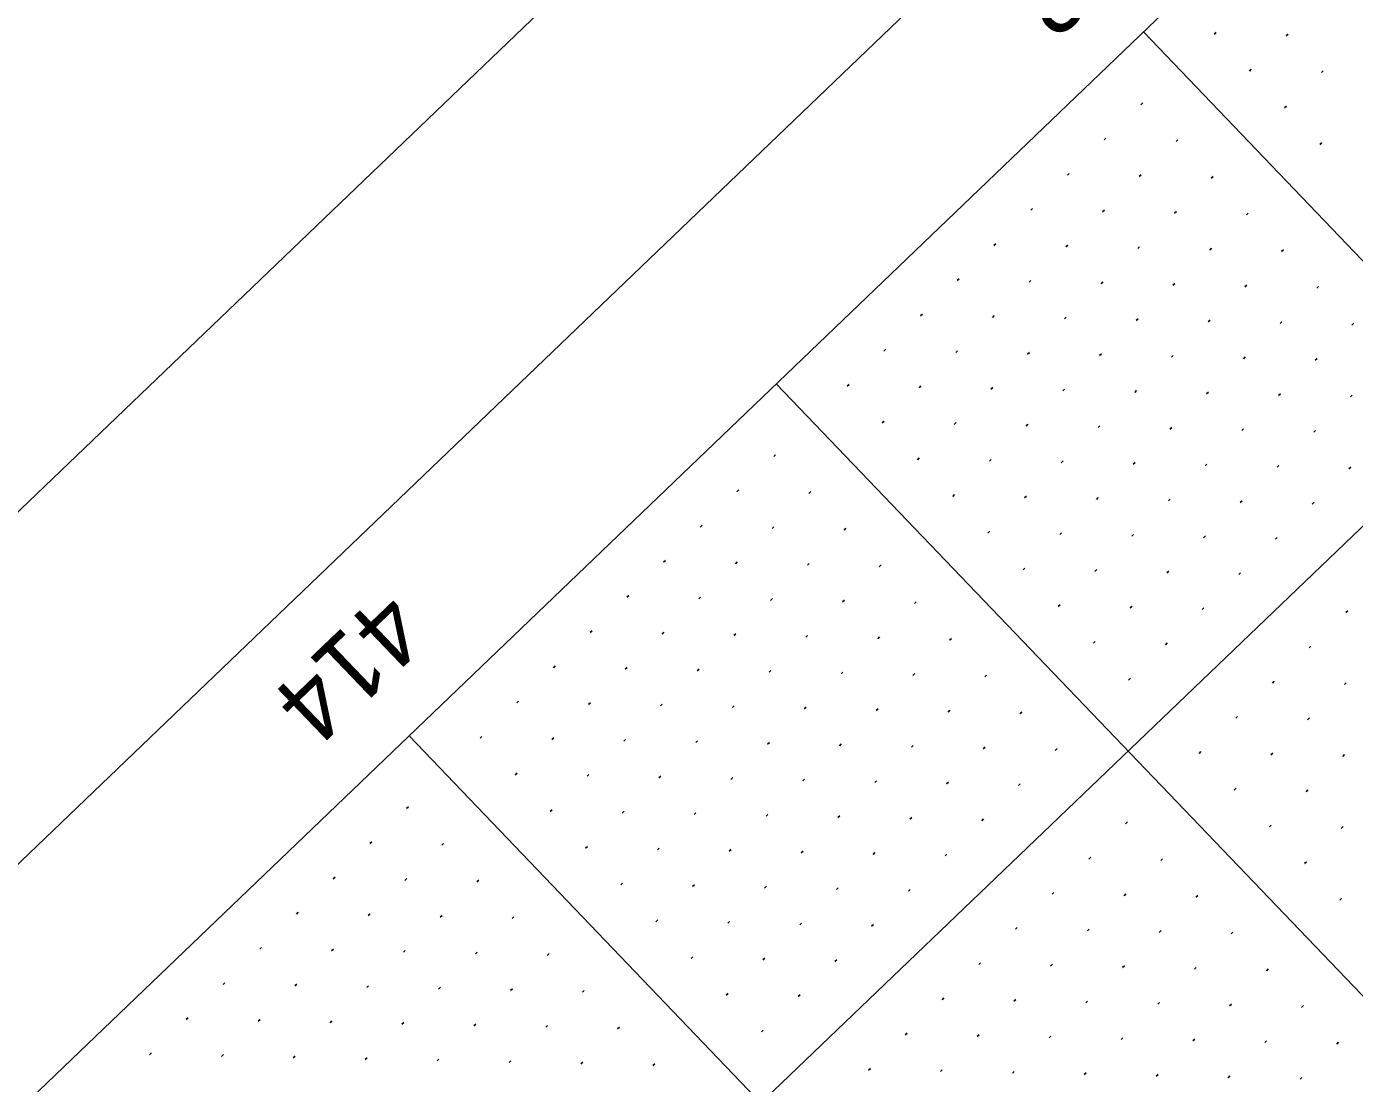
# Model space of a CAD drawing. Extents: x 2148987 to 2151117, y 142806 to 144993.
# Drawn here: x 2149512.9 to 2149643.5, y 144037.5 to 144141.4 of the extents above; entities that cross this region are included whole.
import ezdxf

# ---------------------------------------------------------------- set-up
doc = ezdxf.new("R2010")
doc.units = 0
for name, color, linetype in [('BASELINE', 7, 'Continuous'), ('PR_PIER_PH3', 7, 'Continuous'), ('PR_Road_Concrete', 7, 'Continuous'), ('SHT_Profile_Grid_Minor', 7, 'Continuous'), ('Wall D Bore Txt', 7, 'Continuous')]:
    doc.layers.add(name, color=color, linetype=linetype)

msp = doc.modelspace()

# ---------------------------------------------------------------- linework, layer by layer
at = {"layer": 'BASELINE'}
msp.add_lwpolyline([(2151029.45, 144024.32), (2149802.07, 142848.08), (2149040.98, 143642.27), (2150268.36, 144818.51)], close=True, dxfattribs=at)
at = {"layer": 'PR_PIER_PH3'}
for p, q in [((2150261.97, 144684.26), (2149124.83, 143594.52)), ((2149622.71, 144140.89), (2149916.82, 143833.99)), ((2149622.71, 144140.89), (2149916.82, 143833.99)), ((2149586.61, 144106.3), (2149932.56, 143745.3)), ((2149550.51, 144071.7), (2149896.46, 143710.71))]:
    msp.add_line(p, q, dxfattribs=at)
at = {"layer": 'PR_Road_Concrete'}
msp.add_line((2150227.37, 144720.36), (2149279.76, 143812.24), dxfattribs=at)
msp.add_lwpolyline([(2150941.76, 143974.91), (2149804.63, 142885.16), (2149078.13, 143643.25), (2150215.26, 144733)], close=True, dxfattribs=at)
at = {"layer": 'SHT_Profile_Grid_Minor'}
for p, q in [((2149629.86, 144140.83), (2149629.68, 144140.66)), ((2149636.93, 144140.68), (2149636.75, 144140.51)), ((2149633.32, 144137.22), (2149633.14, 144137.05)), ((2149640.39, 144137.07), (2149640.21, 144136.9)), ((2149622.64, 144133.91), (2149622.46, 144133.74)), ((2149636.78, 144133.61), (2149636.6, 144133.44)), ((2149619.03, 144130.45), (2149618.85, 144130.28)), ((2149626.1, 144130.3), (2149625.92, 144130.13)), ((2149640.24, 144130), (2149640.06, 144129.83)), ((2149615.42, 144126.99), (2149615.24, 144126.82)), ((2149622.49, 144126.84), (2149622.31, 144126.67)), ((2149629.56, 144126.69), (2149629.38, 144126.52)), ((2149611.81, 144123.53), (2149611.63, 144123.36)), ((2149618.88, 144123.38), (2149618.7, 144123.21)), ((2149625.95, 144123.23), (2149625.77, 144123.06)), ((2149633.02, 144123.08), (2149632.84, 144122.91)), ((2149608.2, 144120.07), (2149608.02, 144119.9)), ((2149615.27, 144119.92), (2149615.09, 144119.75)), ((2149622.34, 144119.77), (2149622.16, 144119.6)), ((2149629.41, 144119.62), (2149629.23, 144119.45)), ((2149636.48, 144119.47), (2149636.3, 144119.3)), ((2149604.6, 144116.61), (2149604.41, 144116.44)), ((2149611.66, 144116.46), (2149611.48, 144116.29)), ((2149618.73, 144116.31), (2149618.55, 144116.14)), ((2149625.8, 144116.16), (2149625.62, 144115.99)), ((2149632.87, 144116.01), (2149632.69, 144115.84)), ((2149639.94, 144115.86), (2149639.76, 144115.69)), ((2149600.99, 144113.15), (2149600.8, 144112.98)), ((2149608.05, 144113), (2149607.87, 144112.83)), ((2149615.12, 144112.85), (2149614.94, 144112.68)), ((2149622.19, 144112.7), (2149622.01, 144112.53)), ((2149629.26, 144112.55), (2149629.08, 144112.38)), ((2149636.33, 144112.4), (2149636.15, 144112.23)), ((2149643.4, 144112.25), (2149643.22, 144112.08)), ((2149597.38, 144109.7), (2149597.19, 144109.52)), ((2149604.44, 144109.54), (2149604.26, 144109.37)), ((2149611.51, 144109.39), (2149611.33, 144109.22)), ((2149618.58, 144109.24), (2149618.4, 144109.07)), ((2149625.65, 144109.09), (2149625.47, 144108.92)), ((2149632.72, 144108.94), (2149632.54, 144108.77)), ((2149639.79, 144108.79), (2149639.61, 144108.62)), ((2149593.77, 144106.24), (2149593.58, 144106.06)), ((2149600.83, 144106.09), (2149600.65, 144105.91)), ((2149607.9, 144105.93), (2149607.72, 144105.76)), ((2149614.97, 144105.78), (2149614.79, 144105.61)), ((2149622.04, 144105.63), (2149621.86, 144105.46)), ((2149629.11, 144105.48), (2149628.93, 144105.31)), ((2149636.18, 144105.33), (2149636, 144105.16)), ((2149643.25, 144105.18), (2149643.07, 144105.01)), ((2149597.22, 144102.63), (2149597.04, 144102.45)), ((2149604.29, 144102.48), (2149604.11, 144102.3)), ((2149611.36, 144102.33), (2149611.18, 144102.15)), ((2149618.43, 144102.17), (2149618.25, 144102)), ((2149625.5, 144102.02), (2149625.32, 144101.85)), ((2149632.57, 144101.87), (2149632.39, 144101.7)), ((2149639.64, 144101.72), (2149639.46, 144101.55)), ((2149586.55, 144099.32), (2149586.36, 144099.14)), ((2149600.68, 144099.02), (2149600.5, 144098.84)), ((2149607.75, 144098.87), (2149607.57, 144098.69)), ((2149614.82, 144098.72), (2149614.64, 144098.54)), ((2149621.89, 144098.56), (2149621.71, 144098.39)), ((2149628.96, 144098.41), (2149628.78, 144098.24)), ((2149636.03, 144098.26), (2149635.85, 144098.09)), ((2149643.1, 144098.11), (2149642.92, 144097.94)), ((2149582.94, 144095.86), (2149582.75, 144095.68)), ((2149590, 144095.71), (2149589.82, 144095.53)), ((2149604.14, 144095.41), (2149603.96, 144095.23)), ((2149611.21, 144095.26), (2149611.03, 144095.08)), ((2149618.28, 144095.11), (2149618.1, 144094.93)), ((2149625.35, 144094.95), (2149625.17, 144094.78)), ((2149632.42, 144094.8), (2149632.24, 144094.63)), ((2149639.49, 144094.65), (2149639.31, 144094.48)), ((2149579.33, 144092.4), (2149579.14, 144092.22)), ((2149586.39, 144092.25), (2149586.21, 144092.07)), ((2149593.46, 144092.1), (2149593.28, 144091.92)), ((2149607.6, 144091.8), (2149607.42, 144091.62)), ((2149614.67, 144091.65), (2149614.49, 144091.47)), ((2149621.74, 144091.5), (2149621.56, 144091.32)), ((2149628.81, 144091.34), (2149628.63, 144091.17)), ((2149635.88, 144091.19), (2149635.7, 144091.02)), ((2149575.72, 144088.94), (2149575.53, 144088.77)), ((2149582.78, 144088.79), (2149582.6, 144088.61)), ((2149589.85, 144088.64), (2149589.67, 144088.46)), ((2149596.92, 144088.49), (2149596.74, 144088.31)), ((2149611.06, 144088.19), (2149610.88, 144088.01)), ((2149618.13, 144088.04), (2149617.95, 144087.86)), ((2149625.2, 144087.89), (2149625.02, 144087.71)), ((2149632.27, 144087.73), (2149632.09, 144087.56)), ((2149572.11, 144085.48), (2149571.92, 144085.31)), ((2149579.17, 144085.33), (2149578.99, 144085.16)), ((2149586.24, 144085.18), (2149586.06, 144085)), ((2149593.31, 144085.03), (2149593.13, 144084.85)), ((2149600.38, 144084.88), (2149600.2, 144084.7)), ((2149614.52, 144084.58), (2149614.34, 144084.4)), ((2149621.59, 144084.43), (2149621.41, 144084.25)), ((2149628.66, 144084.28), (2149628.48, 144084.1)), ((2149642.8, 144083.97), (2149642.62, 144083.8)), ((2149568.5, 144082.02), (2149568.32, 144081.85)), ((2149575.56, 144081.87), (2149575.38, 144081.7)), ((2149582.63, 144081.72), (2149582.45, 144081.55)), ((2149589.7, 144081.57), (2149589.52, 144081.39)), ((2149596.77, 144081.42), (2149596.59, 144081.24)), ((2149603.84, 144081.27), (2149603.66, 144081.09)), ((2149617.98, 144080.97), (2149617.8, 144080.79)), ((2149625.05, 144080.82), (2149624.87, 144080.64)), ((2149639.19, 144080.51), (2149639.01, 144080.34)), ((2149564.89, 144078.56), (2149564.71, 144078.39)), ((2149571.96, 144078.41), (2149571.77, 144078.24)), ((2149579.02, 144078.26), (2149578.84, 144078.09)), ((2149586.09, 144078.11), (2149585.91, 144077.94)), ((2149593.16, 144077.96), (2149592.98, 144077.78)), ((2149600.23, 144077.81), (2149600.05, 144077.63)), ((2149607.3, 144077.66), (2149607.12, 144077.48)), ((2149621.44, 144077.36), (2149621.26, 144077.18)), ((2149635.58, 144077.06), (2149635.4, 144076.88)), ((2149642.65, 144076.9), (2149642.47, 144076.73)), ((2149561.28, 144075.1), (2149561.1, 144074.93)), ((2149568.35, 144074.95), (2149568.16, 144074.78)), ((2149575.41, 144074.8), (2149575.23, 144074.63)), ((2149582.48, 144074.65), (2149582.3, 144074.48)), ((2149589.55, 144074.5), (2149589.37, 144074.33)), ((2149596.62, 144074.35), (2149596.44, 144074.18)), ((2149603.69, 144074.2), (2149603.51, 144074.02)), ((2149610.76, 144074.05), (2149610.58, 144073.87)), ((2149631.97, 144073.6), (2149631.79, 144073.42)), ((2149639.04, 144073.45), (2149638.86, 144073.27)), ((2149557.67, 144071.64), (2149557.49, 144071.47)), ((2149564.74, 144071.49), (2149564.55, 144071.32)), ((2149571.8, 144071.34), (2149571.62, 144071.17)), ((2149578.87, 144071.19), (2149578.69, 144071.02)), ((2149585.94, 144071.04), (2149585.76, 144070.87)), ((2149593.01, 144070.89), (2149592.83, 144070.72)), ((2149600.08, 144070.74), (2149599.9, 144070.57)), ((2149607.15, 144070.59), (2149606.97, 144070.41)), ((2149614.22, 144070.44), (2149614.04, 144070.26)), ((2149628.36, 144070.14), (2149628.18, 144069.96)), ((2149635.43, 144069.99), (2149635.25, 144069.81)), ((2149642.5, 144069.84), (2149642.32, 144069.66)), ((2149561.13, 144068.03), (2149560.94, 144067.86)), ((2149568.19, 144067.88), (2149568.01, 144067.71)), ((2149575.26, 144067.73), (2149575.08, 144067.56)), ((2149582.33, 144067.58), (2149582.15, 144067.41)), ((2149589.4, 144067.43), (2149589.22, 144067.26)), ((2149596.47, 144067.28), (2149596.29, 144067.11)), ((2149603.54, 144067.13), (2149603.36, 144066.96)), ((2149610.61, 144066.98), (2149610.43, 144066.8)), ((2149631.82, 144066.53), (2149631.64, 144066.35)), ((2149638.89, 144066.38), (2149638.71, 144066.2)), ((2149550.45, 144064.72), (2149550.27, 144064.55)), ((2149564.58, 144064.42), (2149564.4, 144064.25)), ((2149571.65, 144064.27), (2149571.47, 144064.1)), ((2149578.72, 144064.12), (2149578.54, 144063.95)), ((2149585.79, 144063.97), (2149585.61, 144063.8)), ((2149592.86, 144063.82), (2149592.68, 144063.65)), ((2149599.93, 144063.67), (2149599.75, 144063.5)), ((2149607, 144063.52), (2149606.82, 144063.35)), ((2149621.14, 144063.22), (2149620.96, 144063.04)), ((2149635.28, 144062.92), (2149635.1, 144062.74)), ((2149642.35, 144062.77), (2149642.17, 144062.59)), ((2149546.84, 144061.26), (2149546.66, 144061.09)), ((2149553.91, 144061.11), (2149553.72, 144060.94)), ((2149568.04, 144060.81), (2149567.86, 144060.64)), ((2149575.11, 144060.66), (2149574.93, 144060.49)), ((2149582.18, 144060.51), (2149582, 144060.34)), ((2149589.25, 144060.36), (2149589.07, 144060.19)), ((2149596.32, 144060.21), (2149596.14, 144060.04)), ((2149603.39, 144060.06), (2149603.21, 144059.89)), ((2149617.53, 144059.76), (2149617.35, 144059.58)), ((2149624.6, 144059.61), (2149624.42, 144059.43)), ((2149638.74, 144059.31), (2149638.56, 144059.13)), ((2149543.23, 144057.8), (2149543.05, 144057.63)), ((2149550.3, 144057.65), (2149550.11, 144057.48)), ((2149557.36, 144057.5), (2149557.18, 144057.33)), ((2149571.5, 144057.2), (2149571.32, 144057.03)), ((2149578.57, 144057.05), (2149578.39, 144056.88)), ((2149585.64, 144056.9), (2149585.46, 144056.73)), ((2149592.71, 144056.75), (2149592.53, 144056.58)), ((2149599.78, 144056.6), (2149599.6, 144056.43)), ((2149613.92, 144056.3), (2149613.74, 144056.13)), ((2149620.99, 144056.15), (2149620.81, 144055.97)), ((2149628.06, 144056), (2149627.88, 144055.82)), ((2149642.2, 144055.7), (2149642.02, 144055.52)), ((2149539.62, 144054.34), (2149539.44, 144054.17)), ((2149546.69, 144054.19), (2149546.5, 144054.02)), ((2149553.75, 144054.04), (2149553.57, 144053.87)), ((2149560.82, 144053.89), (2149560.64, 144053.72)), ((2149574.96, 144053.59), (2149574.78, 144053.42)), ((2149582.03, 144053.44), (2149581.85, 144053.27)), ((2149589.1, 144053.29), (2149588.92, 144053.12)), ((2149596.17, 144053.14), (2149595.99, 144052.97)), ((2149610.31, 144052.84), (2149610.13, 144052.67)), ((2149617.38, 144052.69), (2149617.2, 144052.52)), ((2149624.45, 144052.54), (2149624.27, 144052.36)), ((2149631.52, 144052.39), (2149631.34, 144052.21)), ((2149536.01, 144050.88), (2149535.83, 144050.71)), ((2149543.08, 144050.73), (2149542.89, 144050.56)), ((2149550.14, 144050.58), (2149549.96, 144050.41)), ((2149557.21, 144050.43), (2149557.03, 144050.26)), ((2149564.28, 144050.28), (2149564.1, 144050.11)), ((2149578.42, 144049.98), (2149578.24, 144049.81)), ((2149585.49, 144049.83), (2149585.31, 144049.66)), ((2149592.56, 144049.68), (2149592.38, 144049.51)), ((2149606.7, 144049.38), (2149606.52, 144049.21)), ((2149613.77, 144049.23), (2149613.59, 144049.06)), ((2149620.84, 144049.08), (2149620.66, 144048.91)), ((2149627.91, 144048.93), (2149627.73, 144048.75)), ((2149634.98, 144048.78), (2149634.8, 144048.6)), ((2149532.4, 144047.42), (2149532.22, 144047.25)), ((2149539.47, 144047.27), (2149539.28, 144047.1)), ((2149546.53, 144047.12), (2149546.35, 144046.95)), ((2149553.6, 144046.97), (2149553.42, 144046.8)), ((2149560.67, 144046.82), (2149560.49, 144046.65)), ((2149567.74, 144046.67), (2149567.56, 144046.5)), ((2149581.88, 144046.37), (2149581.7, 144046.2)), ((2149588.95, 144046.22), (2149588.77, 144046.05)), ((2149603.09, 144045.92), (2149602.91, 144045.75)), ((2149610.16, 144045.77), (2149609.98, 144045.6)), ((2149617.23, 144045.62), (2149617.05, 144045.45)), ((2149624.3, 144045.47), (2149624.12, 144045.3)), ((2149631.37, 144045.32), (2149631.19, 144045.14)), ((2149528.79, 144043.96), (2149528.61, 144043.79)), ((2149638.44, 144045.17), (2149638.26, 144044.99)), ((2149535.86, 144043.81), (2149535.68, 144043.64)), ((2149542.92, 144043.66), (2149542.74, 144043.49)), ((2149549.99, 144043.51), (2149549.81, 144043.34)), ((2149557.06, 144043.36), (2149556.88, 144043.19)), ((2149564.13, 144043.21), (2149563.95, 144043.04)), ((2149571.2, 144043.06), (2149571.02, 144042.89)), ((2149585.34, 144042.76), (2149585.16, 144042.59)), ((2149599.48, 144042.46), (2149599.3, 144042.29)), ((2149606.55, 144042.31), (2149606.37, 144042.14)), ((2149613.62, 144042.16), (2149613.44, 144041.99)), ((2149620.69, 144042.01), (2149620.51, 144041.84)), ((2149627.76, 144041.86), (2149627.58, 144041.69)), ((2149634.83, 144041.71), (2149634.65, 144041.54)), ((2149641.9, 144041.56), (2149641.72, 144041.38)), ((2149525.18, 144040.51), (2149525, 144040.33)), ((2149532.25, 144040.35), (2149532.07, 144040.18)), ((2149539.32, 144040.2), (2149539.13, 144040.03)), ((2149546.38, 144040.05), (2149546.2, 144039.88)), ((2149553.45, 144039.9), (2149553.27, 144039.73)), ((2149560.52, 144039.75), (2149560.34, 144039.58)), ((2149567.59, 144039.6), (2149567.41, 144039.43)), ((2149574.66, 144039.45), (2149574.48, 144039.28)), ((2149595.87, 144039), (2149595.69, 144038.83)), ((2149602.94, 144038.85), (2149602.76, 144038.68)), ((2149610.01, 144038.7), (2149609.83, 144038.53)), ((2149617.08, 144038.55), (2149616.9, 144038.38)), ((2149624.15, 144038.4), (2149623.97, 144038.23)), ((2149631.22, 144038.25), (2149631.04, 144038.08)), ((2149638.29, 144038.1), (2149638.11, 144037.93))]:
    msp.add_line(p, q, dxfattribs=at)

# ---------------------------------------------------------------- texts
at = {"layer": 'Wall D Bore Txt'}
for s, p in [('413', (2149620.42, 144155.67)), ('414', (2149548.02, 144086.29))]:
    msp.add_text(s, height=7, rotation=223.7809, dxfattribs=at).set_placement(p)

doc.saveas('drawing.dxf')
